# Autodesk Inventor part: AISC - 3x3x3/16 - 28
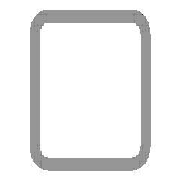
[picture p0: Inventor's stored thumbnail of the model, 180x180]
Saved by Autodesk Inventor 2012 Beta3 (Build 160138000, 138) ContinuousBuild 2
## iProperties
Created: 2011-01
Part Number: AISC - 3x3x3/16 - 28
Material: Steel, Mild
Description: Tube
Document SubType Name: Modeling
Standard: ANSI
Designer: Beta-8540w
Standards Organization: ANSI
Language: en-US
Size Designation: 3x3x3/16
Categories: <MemberInstance><Categories><Category DisplayName="Structural Shapes" InternalName="089c4875-fa83-4c05-b084-43b9cc11f5ed" Mnemonic="GRDR"><CategoryParameter Dis
Stock Number: 3x3x3/16
Density: 7.86 g/cm^3
IsCustomPart: 1
_CCFamilyMember: 9
_CCFamilyDisplayName: ANSI AISC (Square) - Tube
_FrameMemberDoc: Frame Member File
_Version: 15.0.0
_GetPNFromCC: 1
G_L: 28.000 in
G_W: 3.000 in
G_H: 3.000 in
Author: Beta-8540w
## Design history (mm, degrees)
node "Start plane"
node "End plane"
sketch "Sketch"
  geometry: L1 (-38.1, -28.575)-(-38.1, 28.575); L2 (-28.575, 38.1)-(28.575, 38.1); L3 (38.1, 28.575)-(38.1, -28.575); L4 (28.575, -38.1)-(-28.575, -38.1); L5 (-28.575, 33.337)-(28.575, 33.338); L6 (33.338, 28.575)-(33.338, -28.575); L7 (28.575, -33.337)-(-28.575, -33.338); L8 (-33.338, -28.575)-(-33.338, 28.575); L9 (0, 56.102)-(0, -56.102) reference; L10 (-56.102, 0)-(56.102, 0) reference; A1 r 9.525 centre (-28.575, -28.575) between (-38.1, -28.575) and (-28.575, -38.1); A2 r 9.525 centre (-28.575, 28.575) between (-28.575, 38.1) and (-38.1, 28.575); A3 r 9.525 centre (28.575, 28.575) between (38.1, 28.575) and (28.575, 38.1); A4 r 9.525 centre (28.575, -28.575) between (28.575, -38.1) and (38.1, -28.575); A5 r 4.763 centre (-28.575, 28.575) between (-28.575, 33.337) and (-33.338, 28.575); A6 r 4.763 centre (28.575, 28.575) between (33.338, 28.575) and (28.575, 33.338); A7 r 4.763 centre (28.575, -28.575) between (28.575, -33.337) and (33.338, -28.575); A8 r 4.763 centre (-28.575, -28.575) between (-33.338, -28.575) and (-28.575, -33.338)
  constraints: 16 end point, 16 point on circle, 8 centre point, 8 tangent, 4 parallel, 3 equal radius, 2 perpendicular, 7 other
  dimensions: "d10" = 76.2 distance between parallel lines of L2 L4 (= G_H); "d11" = 76.2 distance between parallel lines of L1 L3 (= G_W); "d12" = 4.7625 distance between parallel lines of L3 L6 (= G_T); "d15" = 38.1 distance between parallel lines of L2 L10 (= 0.5 x d10); "d16" = 38.1 distance between parallel lines of L9 L3 (= 0.5 x d11); "d17" = 9.525 radius of A1 (= G_IR)
extrude "Body" new body sketch "Sketch" stored distance "d3" = 711.2 (= G_L); taper "d4" = 0 deg
node "Driven Length"
  sketch "Sketch3"
    geometry: L1 (0, 0)-(10, 0) reference
    constraints: 2 end point, 1 horizontal
  workplane "Work Plane3"
  sketch "Sketch4"
    geometry: L1 (-2, 0)-(12, 0) reference; L2 (-2, 711.2)-(12, 711.2) reference
    dimensions: "d19" = 711.2 distance between parallel lines of L1 L2 (derived)
body "Solid1"
other parameters: "G_W" = 76.2 [user parameter; used in 1 equation term], "G_H" = 76.2 [user parameter; used in 1 equation term], "G_T" = 4.7625 [user parameter; used in 1 equation term], "G_IR" = 9.525 [user parameter; used in 1 equation term], "G_L" = 711.2 (= d19) [user parameter; used in 1 equation term], "G_OFFSET_START" = 0 [user parameter; used in 1 equation term], "G_OFFSET_END" = 0 [user parameter; used in 1 equation term], "d13" = 0 (computed from G_OFFSET_START), "d14" = 711.2 (= G_OFFSET_END + B_L), "B_L" = 711.2 [user parameter; used in 1 equation term], "d18" = 90 deg
